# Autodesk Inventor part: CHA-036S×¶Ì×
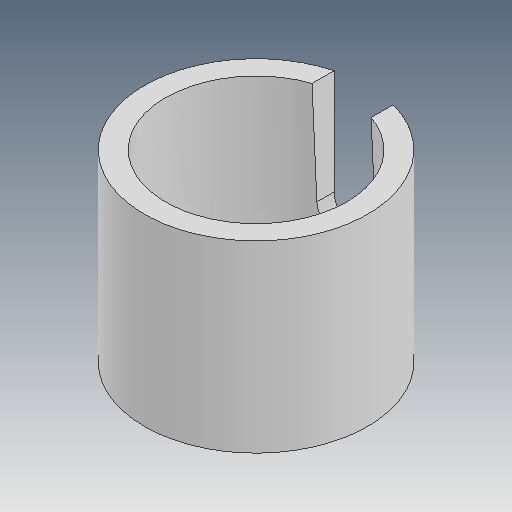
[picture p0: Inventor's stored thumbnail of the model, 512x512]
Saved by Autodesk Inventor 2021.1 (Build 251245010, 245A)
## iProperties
Created: 2019-12
Part Number: CHA-036S×¶Ì×
Material: Ogólny
Document SubType Name: Modeling
Designer: user
Density: 1 g/cm^3
Appearance: Domyślna
Author: user
Revision Number: ÈÎºÎ
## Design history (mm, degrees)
feature "ÊäÈë1"
node "Bryła1"
